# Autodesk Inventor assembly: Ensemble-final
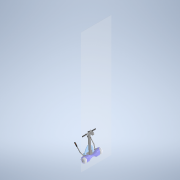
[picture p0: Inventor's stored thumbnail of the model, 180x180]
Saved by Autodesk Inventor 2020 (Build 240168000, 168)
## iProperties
Created: 2022-10
Part Number: Ensemble-final
Document SubType Name: Assembly
Designer: bruno
Author: bruno
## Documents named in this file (6)
- C:\Users\bruno\Documents\1-Cours-2022-23\1SI\2. Cinématique\Hoverboard\Inventor-Hoverboard\Ensemble-final.iam
- C:\Users\bruno\Documents\1-Cours-2022-23\1SI\2. Cinématique\Hoverboard\Inventor-Hoverboard\Ensemble-final-corps.iam
- C:\Users\bruno\Documents\1-Cours-2022-23\1SI\2. Cinématique\Hoverboard\Inventor-Hoverboard\Wheel.ipt
- C:\Users\bruno\Documents\1-Cours-2022-23\1SI\2. Cinématique\Hoverboard\Inventor-Hoverboard\Sol.ipt
- C:\Users\bruno\Documents\1-Cours-2022-23\1SI\2. Cinématique\Hoverboard\Inventor-Hoverboard\Roue-avant.ipt
- C:\Users\bruno\Documents\1-Cours-2022-23\1SI\2. Cinématique\Hoverboard\Inventor-Hoverboard\Wheel-2.ipt
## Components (5 placed, 5 different names)
1. Ensemble-final-corps:1 [sub-assembly] — Logement:2, Logement:3, Logement:4
2. Wheel:2 — Logement:2
3. Sol:1 — Tangente:1
4. Roue-avant:1 — Logement:3
5. Wheel-2:1 — Logement:4, Tangente:1
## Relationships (4: Insert 3, Tangent 1)
- Logement:2 [Insert]: Ensemble-final-corps:1 ↔ Wheel:2
- Logement:3 [Insert]: Ensemble-final-corps:1 ↔ Roue-avant:1
- Logement:4 [Insert]: Ensemble-final-corps:1 ↔ Wheel-2:1
- Tangente:1: Sol:1 ↔ Wheel-2:1
